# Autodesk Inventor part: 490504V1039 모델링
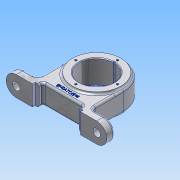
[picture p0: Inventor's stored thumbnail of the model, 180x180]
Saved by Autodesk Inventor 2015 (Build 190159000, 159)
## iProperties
Created: 2019-05
Part Number: 490504V1039 모델링
Material: 알루미늄 6061
Document SubType Name: Modeling
Designer: user
Density: 2.7 g/cm^3
Appearance: 알루미늄 - 평지
Mass: 455.971 g
Surface Area: 318.89 cm^2
Volume: 168.878 cm^3
Author: user
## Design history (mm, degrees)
sketch "스케치1"
  geometry: L1 (-75, -60)-(75, -60); L2 (-40, 0)-(-40, -48); L3 (40, 0)-(40, -48); L4 (-75, -48)-(-75, -60); L5 (75, -48)-(75, -60); L6 (75, -48)-(40, -48); L7 (-40, -48)-(-75, -48); A1 r 40 centre (0, 0) between (40, 0) and (-40, 0); 1 further point
  constraints: 14 end point, 2 point on circle, 1 centre point, 1 coincident, 1 parallel, 1 vertical
  dimensions: "d0" = 80 diameter of A1; "d3" = 150 distance between parallel lines of L5 L4
extrude "돌출1" new body sketch "스케치1" stored distance "d5" = 30; taper "d6" = 0 deg
fillet "모깎기1" dims "d7" = 15
node "작업 평면1"
sketch "스케치2"
  geometry: C1 r 36 at (0, 0); 1 further point
  constraints: 1 centre point, 1 coincident
  dimensions: "d9" = 72 diameter of C1
extrude "돌출2" join sketch "스케치2" stored distance "d10" = 36; taper "d11" = 0 deg
fillet "모깎기3" dims "d13" = 3
sketch "스케치3"
  geometry: C1 r 26 at (0, 0); A1 r 36 centre (0, 0) between (36, 0) and (36, 0) reference
  constraints: 1 centre point, 1 coincident
  dimensions: "d14" = 52 diameter of C1
extrude "돌출3" cut sketch "스케치3" stored distance "d15" = 36; taper "d16" = 0 deg
sketch "스케치4"
  geometry: L1 (-60, -60)-(60, -60) reference; L2 (-36, -60)-(36, -60); L3 (36, -60)-(36, -56); L4 (-36, -56)-(-36, -60); L5 (-30, -60)-(30, -60); L6 (30, -56)-(30, -50); L7 (30, -50)-(-30, -50); L8 (-30, -50)-(-30, -56); L9 (36, -56)-(30, -56); L10 (-30, -56)-(-36, -56); 6 further points
  constraints: 18 end point, 6 midpoint, 5 parallel, 4 coincident, 2 horizontal, 2 perpendicular
  dimensions: "d17" = 72 distance of L2.start L2.end; "d18" = 4 distance of L4.start L2.start; "d19" = 60 distance of L7.end L6.end; "d20" = 10 distance of L6.end L5.end
extrude "돌출4" cut sketch "스케치4" stored distance "d21" = 36; taper "d22" = 0 deg
fillet "모깎기4" dims "d23" = 3
fillet "모깎기5" dims "d24" = 6
fillet "모깎기6" dims "d25" = 3
sketch "스케치5"
  geometry: C1 r 9 at (0, -12); A1 r 12 centre (0, -12) between (0, 0) and (0, -24) reference; 1 further point
  constraints: 1 centre point, 1 coincident
  dimensions: "d26" = 18 diameter of C1
extrude "돌출5" join sketch "스케치5" distance "d27" = 3; taper "d28" = 0 deg
fillet "모깎기7" dims "d29" = 3
sketch "스케치6"
  geometry: C1 r 9 at (0, 0) reference; C2 r 5.5 at (0, 0); 1 further point
  constraints: 1 centre point, 1 coincident
  dimensions: "d30" = 11 diameter of C2
extrude "돌출6" cut sketch "스케치6" stored distance "d31" = 3; taper "d32" = 0 deg
node "작업 평면2"
fillet "모깎기8" dims "d34" = 3
fillet "모깎기9" dims "d35" = 3
sketch "스케치7"
  geometry: L1 (0, 0)-(0, 26); C1 r 36 at (0, 0) reference; C2 r 1.5 at (0, 26); 1 further point
  constraints: 2 end point, 1 centre point, 1 coincident, 1 vertical, 1 vertical alignment, 1 other
  dimensions: "d36" = 3 diameter of C2
extrude "돌출7" cut sketch "스케치7" stored distance "d37" = 3; taper "d38" = 0 deg
node "작업 평면3"
node "작업 평면4"
sketch "스케치9"
  geometry: L1 (0, -50)-(0, -43); L2 (-21.166, -39.71)-(21.166, -39.71); L3 (21.166, -39.71)-(21.166, -46.29); L4 (21.166, -46.29)-(-21.166, -46.29); L5 (-21.166, -46.29)-(-21.166, -39.71); 3 further points
  constraints: 2 end point, 2 horizontal alignment, 2 midpoint, 1 vertical, 1 vertical alignment, 2 other
  dimensions: "d52" = 7 distance of L1.start L1.end
extrude "돌출8" join sketch "스케치9" distance "d53" = 0.5; taper "d54" = 0 deg
chamfer "모따기1" distance "d55" = 1; stored, may be unused: second distance "d56" = 2, angle "d57" = 45 deg
sketch "스케치10"
  geometry: 1 further point
hole "구멍2" sketch "스케치10" at (0, 0) diameter "d58" = 4.917; stored, may be unused: countersink angle "d62" = 82 deg, drill point angle "d64" = 118 deg; dims "d59" = 8, "d60" = 7, "d61" = 1, "d63" = 10
sketch "스케치11"
  geometry: L1 (65.5, -60)-(65.5, -45) reference; L2 (65.5, -45)-(69, -45) reference; L3 (75, -51)-(75, -60) reference; L4 (75, -60)-(65.5, -60) reference; L5 (-69, -45)-(-65.5, -45) reference; L6 (-65.5, -45)-(-65.5, -60) reference; L7 (-65.5, -60)-(-75, -60) reference; L8 (-75, -60)-(-75, -51) reference; L9 (40, 0)-(40, -42) reference; L10 (46, -48)-(48, -48) reference; L11 (51, -45)-(54.5, -45) reference; L12 (54.5, -45)-(54.5, -60) reference; L13 (54.5, -60)-(36, -60) reference; L14 (36, -60)-(36, -56) reference; L15 (36, -56)-(30, -56) reference; L16 (30, -56)-(30, -53) reference; L17 (27, -50)-(-27, -50) reference; L18 (-30, -53)-(-30, -56) reference; L19 (-30, -56)-(-36, -56) reference; L20 (-36, -56)-(-36, -60) reference; L21 (-36, -60)-(-54.5, -60) reference; L22 (-54.5, -60)-(-54.5, -45) reference; L23 (-54.5, -45)-(-51, -45) reference; L24 (-48, -48)-(-46, -48) reference; L25 (-40, -42)-(-40, 0) reference; L26 (-3.5, 39.847)-(-3.5, 39) reference; L27 (-3.5, 39)-(-2.458, 39) reference; L28 (-2.458, 39)-(-2.458, 29) reference; L29 (-2.458, 29)-(0, 27.523) reference; L30 (0, 27.523)-(2.458, 29) reference; L31 (2.458, 29)-(2.458, 39) reference; L32 (2.458, 39)-(3.5, 39) reference; L33 (3.5, 39)-(3.5, 39.847) reference; L34 (-1, 28.144)-(0, 28.144); L35 (0, 24.508)-(-1, 24.508); L36 (-1, 24.508)-(-1, 28.144); L37 (0, 28.144)-(0, 24.508); A1 r 26 centre (0, 0) between (-1.499, 25.957) and (1.499, 25.957) reference; A2 r 1.5 centre (0, 26) between (1.499, 25.957) and (-1.499, 25.957) reference; A3 r 3 centre (72, -45) between (69, -45) and (72, -48) reference; A4 r 3 centre (72, -51) between (75, -51) and (72, -48) reference; A5 r 3 centre (-72, -45) between (-72, -48) and (-69, -45) reference; A6 r 3 centre (-72, -51) between (-72, -48) and (-75, -51) reference; A7 r 6 centre (46, -42) between (40, -42) and (46, -48) reference; A8 r 3 centre (48, -45) between (48, -48) and (51, -45) reference; A9 r 3 centre (27, -53) between (30, -53) and (27, -50) reference; A10 r 3 centre (-27, -53) between (-27, -50) and (-30, -53) reference; A11 r 3 centre (-48, -45) between (-51, -45) and (-48, -48) reference; A12 r 6 centre (-46, -42) between (-46, -48) and (-40, -42) reference; A13 r 40 centre (0, 0) between (-3.5, 39.847) and (-40, 0) reference; A14 r 40 centre (0, 0) between (40, 0) and (3.5, 39.847) reference; 1 further point
  constraints: 8 end point, 1 horizontal, 1 parallel, 1 vertical alignment
revolve "회전1" sketch "스케치11" stored, may be unused: angle "d67" = 90 deg
sketch "스케치12" dims "d68" = 62
  geometry: L1 (0, 0)-(-31, 0); C1 r 36 at (0, 0) reference
  constraints: 2 end point, 1 coincident, 1 horizontal, 1 horizontal alignment, 2 other
hole "구멍3" sketch "스케치12" at (-31, 0) diameter "d69" = 3.242; stored, may be unused: countersink angle "d73" = 90 deg, drill point angle "d75" = 118 deg; dims "d70" = 6, "d71" = 4, "d72" = 2, "d74" = 8
node "솔리드1"
mirror "대칭1"
pattern_circular "원형 패턴2" dims angle "d77" = 360 deg
mirror "대칭3"
node "절단 모서리 투영1"
other parameters: "d4" = 12, "d8" = 0, "d33" = 0, "d50" = 0
